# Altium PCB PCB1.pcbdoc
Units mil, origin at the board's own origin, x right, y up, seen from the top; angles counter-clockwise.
Board outline 2210 x 2265.36 mil, 2 copper layers (Top Layer, Bottom Layer); 43 components, 41 nets, 201 pads, 91 vias.
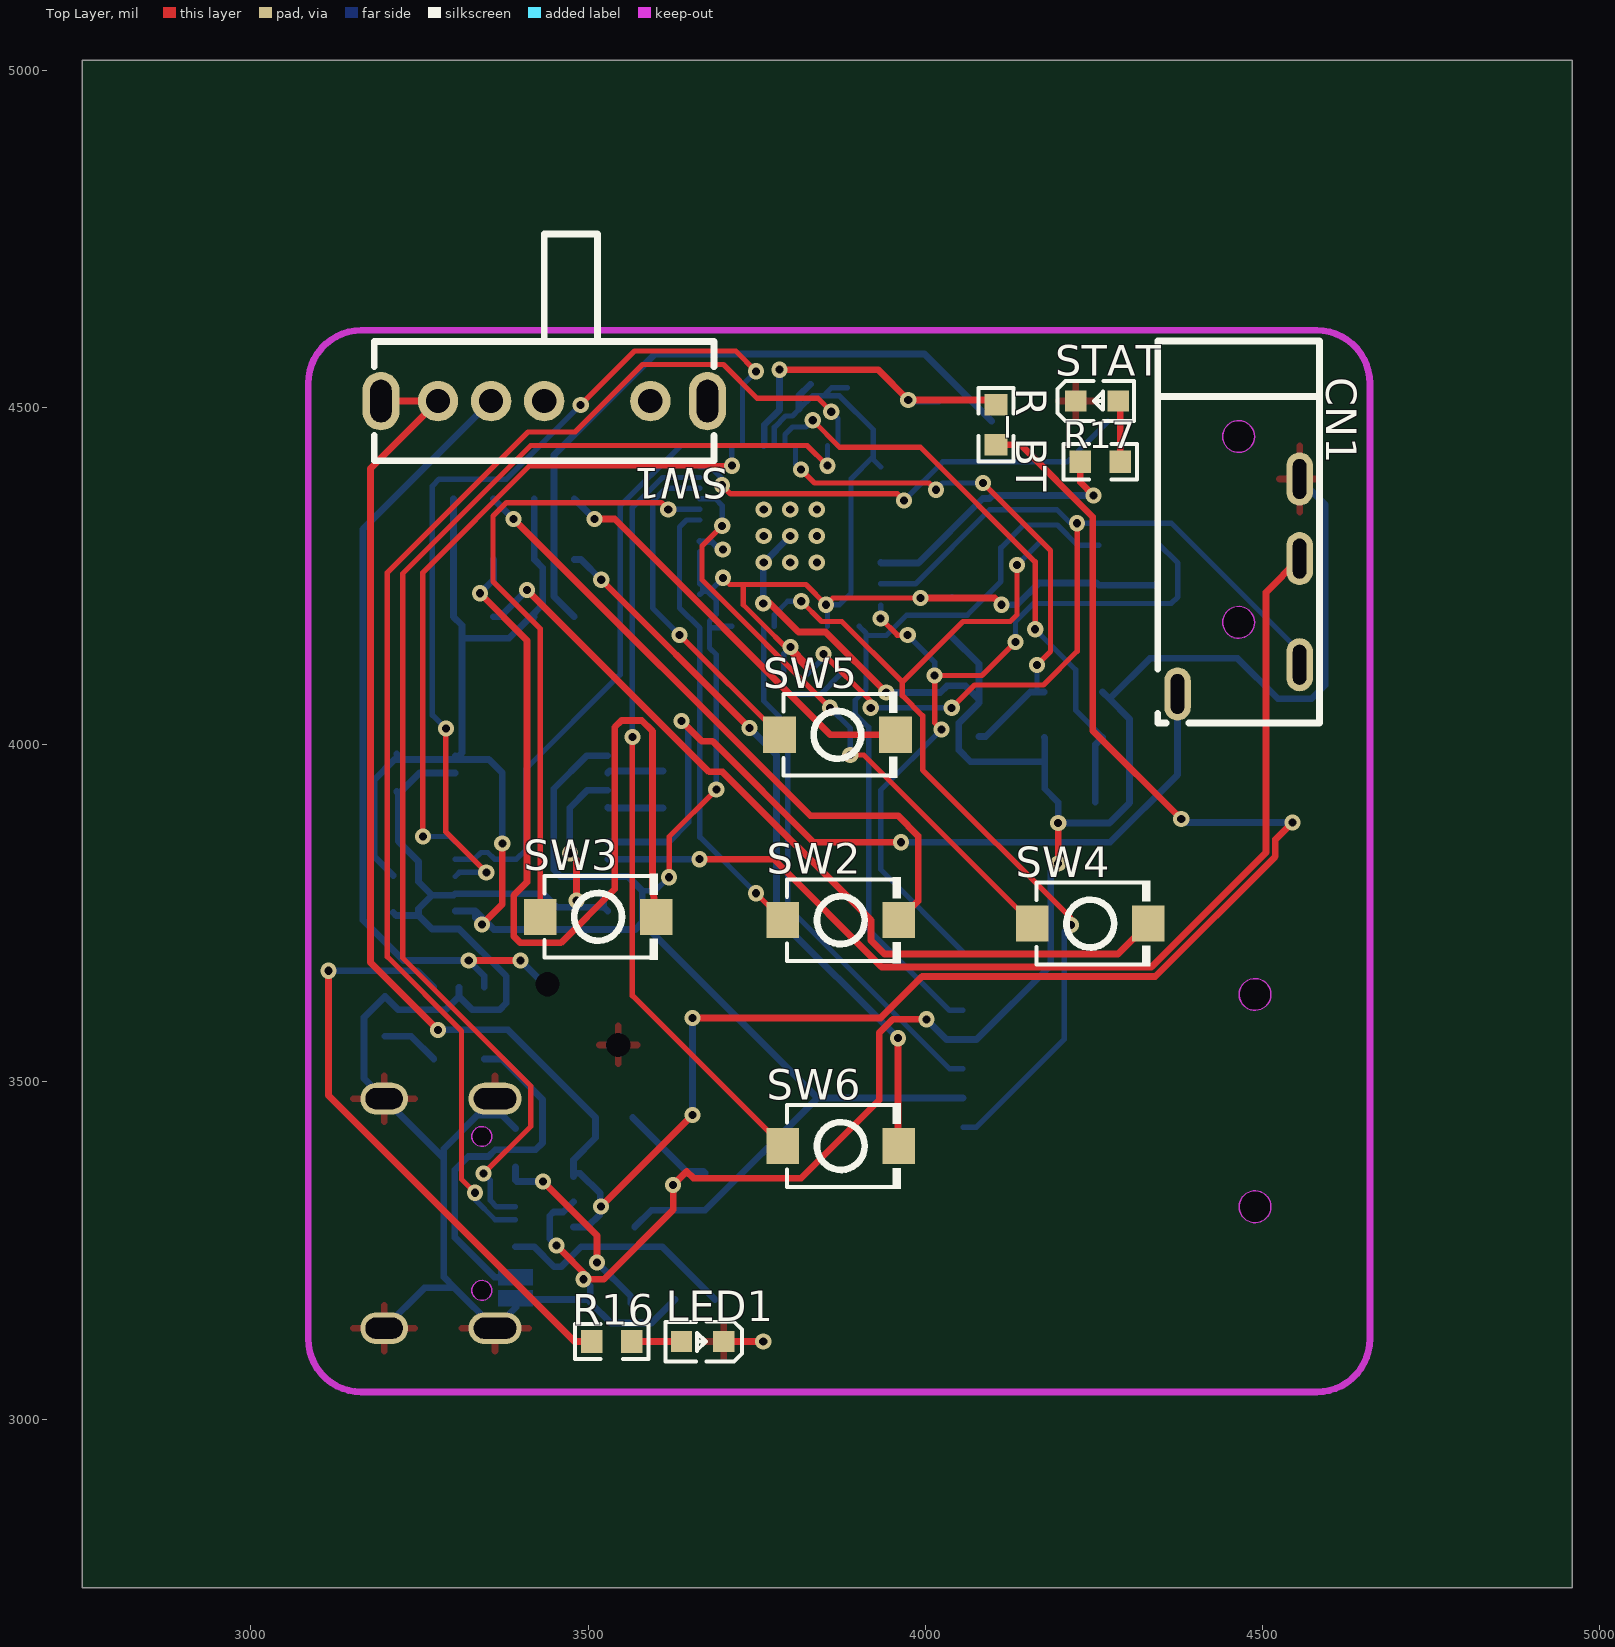
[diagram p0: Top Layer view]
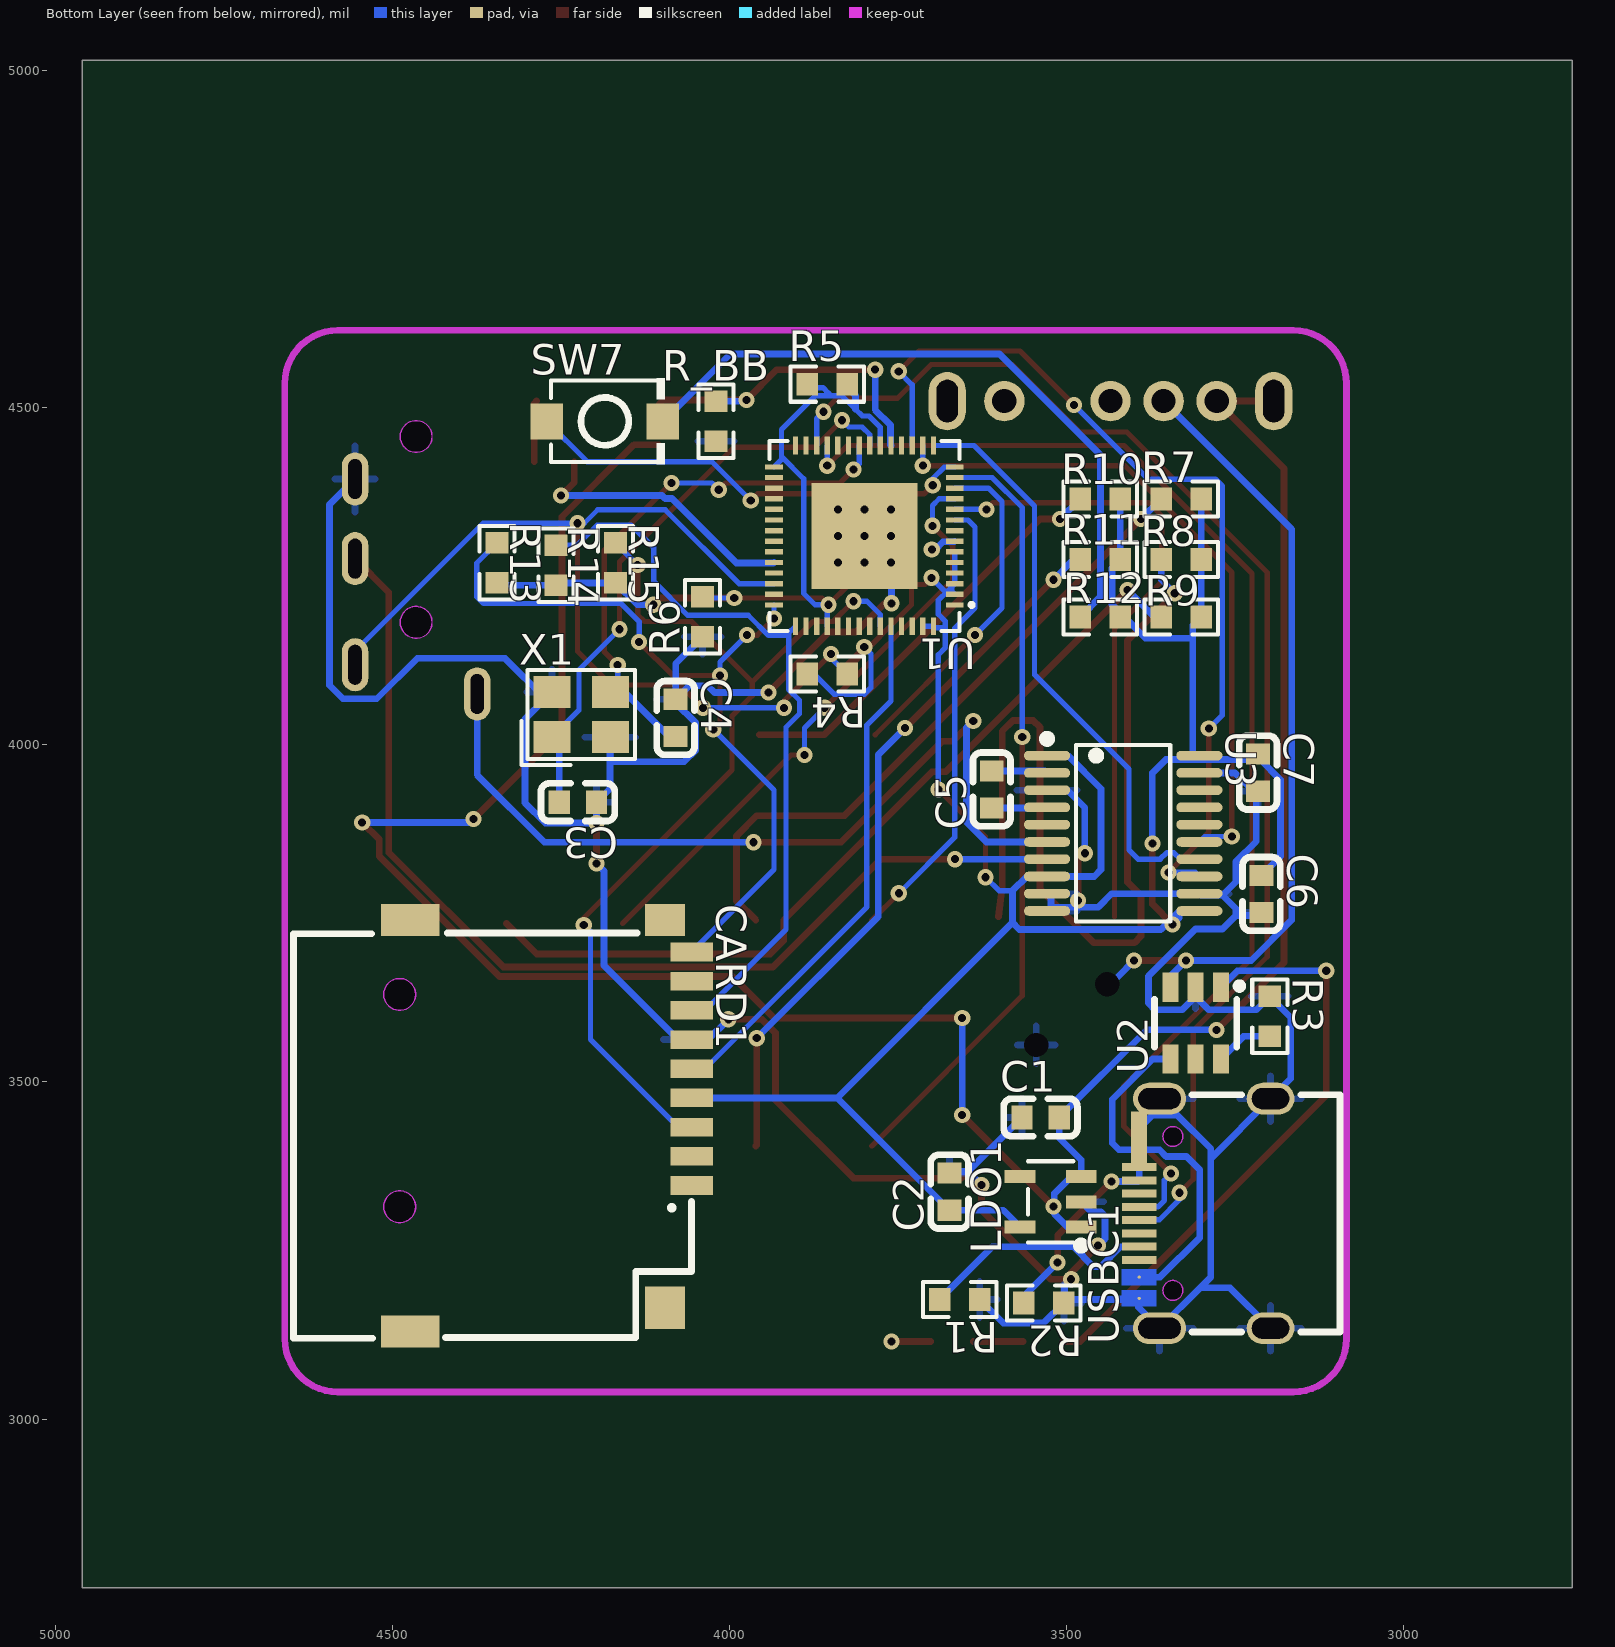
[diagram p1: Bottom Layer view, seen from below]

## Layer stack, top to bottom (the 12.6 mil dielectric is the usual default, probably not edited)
Top Layer: signal copper (thickness not stored)
Dielectric: dielectric 12.6, FR-4, Dk 4.8
Bottom Layer: signal copper (thickness not stored)

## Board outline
4960,2750 2750,2750 2750,5015.36 4960,5015.36

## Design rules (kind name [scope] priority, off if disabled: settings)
BoardOutlineClearance copperThickness1oz [All] p0: genericclearance=10 ignorepadtopadclearanceinfootprint=FALSE except(0: Arc-SplitContinuation Track-SplitContinuation SMDPad-SplitContinuation THPad-SplitContinuation Via-SplitContinuation Fill-SplitContinuation Poly-SplitContinuation Region-SplitContinuation Text-SplitContinuation; 6: Track-CutoutEdge SMDPad-CutoutEdge THPad-CutoutEdge Via-CutoutEdge Region-CutoutEdge; 11.8: Track-OutlineEdge SMDPad-OutlineEdge THPad-OutlineEdge Via-OutlineEdge Fill-OutlineEdge Region-OutlineEdge Poly-OutlineEdge Text-OutlineEdge Fill-CutoutEdge)
BoardOutlineClearance copperThickness2oz [All] p0: genericclearance=10 ignorepadtopadclearanceinfootprint=FALSE except(0: Arc-SplitContinuation Track-SplitContinuation SMDPad-SplitContinuation THPad-SplitContinuation Via-SplitContinuation Fill-SplitContinuation Poly-SplitContinuation Region-SplitContinuation Text-SplitContinuation; 6: Track-CutoutEdge SMDPad-CutoutEdge THPad-CutoutEdge Via-CutoutEdge Region-CutoutEdge; 11.8: Track-OutlineEdge SMDPad-OutlineEdge THPad-OutlineEdge Via-OutlineEdge Fill-OutlineEdge Region-OutlineEdge Poly-OutlineEdge Text-OutlineEdge Fill-CutoutEdge)
Clearance copperThickness1oz [(InNet('V_LDO_IN') OR InNet('GND') OR InNet('VCC') OR InNet('$1N1223') OR InNet('$1N1229') OR InNet('$1N2848') OR InNet('$1N2853') OR InNet('TF_DATA0') OR InNet('TF_CLX') OR InNet('TF_CMD') OR InNet('TF_CD') OR InNet('OUTR') OR InNet('GPIO35') OR InNet('OUTL') OR InNet('$1N2072') OR InNet('$1N2076') OR InNet('$1N2223') OR InNet('$1N3768') OR InNet('$1N3800') OR InNet('$1N3832') OR InNet('$1N3864') OR InNet('$1N3896') OR InNet('$1N3928') OR InNet('V_BAT') OR InNet('B1') OR InNet('B2') OR InNet('B3') OR InNet('B4') OR InNet('B5') OR InNet('B6') OR InNet('I2S_DATA') OR InNet('I2S_LRCK') OR InNet('I2S_BCK') OR InNet('USB_DN') OR InNet('USB_DP') OR InNet('V_USB') OR InNet('$1N4567') OR InNet('$1N4573') OR InNet('ADC') OR InNet('LED_STAT') OR InNet('$1N5751'))] p1: gap=7 ignorepadtopadclearanceinfootprint=FALSE except(4: Track-Track; 6: Track-SMDPad SMDPad-SMDPad Track-THPad SMDPad-THPad THPad-THPad Track-Via SMDPad-Via THPad-Via Via-Via SMDPad-Fill THPad-Fill Via-Fill Fill-Fill Track-Region SMDPad-Region THPad-Region Via-Region Region-Region Track-Poly SMDPad-Poly THPad-Poly Via-Poly Fill-Poly Region-Poly Poly-Poly Track-Text SMDPad-Text THPad-Text Via-Text Fill-Text Region-Text Poly-Text Text-Text; 6.9: Track-Hole SMDPad-Hole THPad-Hole Via-Hole Fill-Hole Region-Hole Poly-Hole Text-Hole Sheet-Hole; 11.8: Track-Fill Fill-Region Track-Sheet SMDPad-Sheet THPad-Sheet Via-Sheet Fill-Sheet Region-Sheet Poly-Sheet Text-Sheet)
Clearance copperThickness2oz [All] p1: gap=7 ignorepadtopadclearanceinfootprint=FALSE except(6: Track-SMDPad SMDPad-SMDPad Track-THPad SMDPad-THPad THPad-THPad Track-Via SMDPad-Via THPad-Via Via-Via SMDPad-Fill THPad-Fill Via-Fill Fill-Fill Track-Region SMDPad-Region THPad-Region Via-Region Region-Region Track-Poly SMDPad-Poly THPad-Poly Via-Poly Fill-Poly Region-Poly Poly-Poly Track-Text SMDPad-Text THPad-Text Via-Text Fill-Text Region-Text Poly-Text Text-Text; 6.9: Track-Hole SMDPad-Hole THPad-Hole Via-Hole Fill-Hole Region-Hole Poly-Hole Text-Hole Sheet-Hole; 8: Track-Track; 11.8: Track-Fill Fill-Region Track-Sheet SMDPad-Sheet THPad-Sheet Via-Sheet Fill-Sheet Region-Sheet Poly-Sheet Text-Sheet)
DiffPairsRouting differentialPair [All] p1: maxuncoupledlength=10 minlimit=6 maxlimit=6 mostfreqgap=6 toplayer_minwidth=5 toplayer_prefwidth=10 toplayer_maxwidth=100 bottomlayer_minwidth=5 bottomlayer_prefwidth=10 bottomlayer_maxwidth=100
PasteMaskExpansion pasteMaskExpansion [All] p1: expansion=0
PlaneConnect innerPlane [All] p1: planeconnectstyle=Relief reliefexpansion=20 reliefentries=4 reliefconductorwidth=10 reliefairgap=10
PolygonConnect copperRegion [All] p1: connectstyle=Relief reliefentries=4 reliefconductorwidth=10 polygonreliefangle="90 Angle" airgapwidth=10
RoutingVias viaSize [All] p1: viastyle="Through Hole" holewidth=12.0078 minholewidth=11.811 maxholewidth=248.0314 width=24.0158 minwidth=19.685 maxwidth=393.7008
SolderMaskExpansion solderMaskExpansion [All] p1: useseparateexpansions=TRUE expansion=2 expansionbottom=2
Width copperThickness1oz [All] p1: maxlimit=100 minlimit=5 preferedwidth=10
Width copperThickness2oz [All] p1: maxlimit=100 minlimit=8 preferedwidth=10

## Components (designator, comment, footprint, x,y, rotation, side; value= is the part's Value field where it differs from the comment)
C1 "CL10A106MA8NRNC" C0603 3538.72,3447.33 r180 bottom
C2 "CL10A106MA8NRNC" C0603 3673.72,3337.33 r90 bottom
C3 "CL10C100JB8NNNC" C0603 4225,3915 r0 bottom
C4 "CL10C100JB8NNNC" C0603 4080,4040 r270 bottom
C5 "CL10B104KB8NNNC" C0603 3611.11,3933.89 r90 bottom
C6 "CL10B104KB8NNNC" C0603 3211.11,3778.89 r270 bottom
C7 "CL10B104KB8NNNC" C0603 3216.11,3958.89 r270 bottom
CARD1 "TF PUSH" TF-SMD_TF-PUSH 4265,3435 r270 bottom
CN1 "PJ-320A_C49284721" AUDIO-TH_PJ-320A_C49284721 4465,4235 r270 top
LDO1 "ME6211C33M5G-N" SOT-23-5_L3.0-W1.7-P0.95-LS2.8-BL 3523.72,3322.33 r90 bottom
LED1 "NCD0603Y2" LED0603-RD 3670,3115 r180 top
R1 "0603WAF5101T5E" R0603 3658.72,3177.33 r0 bottom
R2 "0603WAF5101T5E" R0603 3533.72,3172.33 r0 bottom
R3 "ERA3AEB162V" R0603 3198.72,3597.33 r270 bottom
R4 "0603WAF1002T5E" R0603 3855,4105 r0 bottom
R5 "0603WAF1002T5E" R0603 3855,4535 r180 bottom
R6 "0603WAF1002T5E" R0603 4040,4190 r90 bottom
R7 "0603WAF1002T5E" R0603 3330,4365 r180 bottom
R8 "0603WAF1002T5E" R0603 3330,4275 r180 bottom
R9 "0603WAF1002T5E" R0603 3330,4190 r180 bottom
R10 "0603WAF1002T5E" R0603 3450,4365 r180 bottom
R11 "0603WAF1002T5E" R0603 3450,4275 r180 bottom
R12 "0603WAF1002T5E" R0603 3450,4190 r180 bottom
R13 "0603WAF1002T5E" R0603 4345,4270 r270 bottom
R14 "0603WAF1002T5E" R0603 4257.65,4266.48 r270 bottom
R15 "0603WAF1002T5E" R0603 4169.01,4270 r270 bottom
R16 "FRC0603J221 TS" R0603 3535,3115 r0 top
R17 "Res_0603" R0603 4260,4420 r0 top
R_BB "Res_0603" R0603 4020,4480 r270 bottom
R_BT "Res_0603" R0603 4105,4475 r90 top
STAT "NCD0603Y2" LED0603-RD 4255,4510 r0 top
SW1 "SK13D07VG4" SW-TH_SK13D07VG4 3435,4510 r180 top
SW2 "TS-1088-AR02016" SW-SMD_L3.9-W3.0-P4.45 3875,3740 r0 top
SW3 "TS-1088-AR02016" SW-SMD_L3.9-W3.0-P4.45 3515,3745 r0 top
SW4 "TS-1088-AR02016" SW-SMD_L3.9-W3.0-P4.45 4245,3735 r0 top
SW5 "TS-1088-AR02016" SW-SMD_L3.9-W3.0-P4.45 3870,4015 r0 top
SW6 "TS-1088-AR02016" SW-SMD_L3.9-W3.0-P4.45 3875,3405 r0 top
SW7 "TS-1088-AR02016" SW-SMD_L3.9-W3.0-P4.45 4185,4480 r180 bottom
U1 "ESP32-S3R8" QFN-56_L7.0-W7.0-P0.40-TL-EP4.0 3800,4310 r0 bottom
U2 "TP4057" SOT-23-6_L2.9-W1.6-P0.95-LS2.8-BR 3308.72,3587.33 r90 bottom
U3 "PCM5100APWR" TSSOP-20_L6.5-W4.4-P0.65-LS6.4-BL 3416.11,3868.89 r270 bottom
USBC1 "TYPE-C-31-M-12" USB-C_SMD-TYPE-C-31-M-12_1 3295,3305 r90 bottom
X1 "XL2EL89CPI-111YLC-40M" CRYSTAL-SMD_4P-L3.2-W2.5-BL 4220,4045 r180 bottom

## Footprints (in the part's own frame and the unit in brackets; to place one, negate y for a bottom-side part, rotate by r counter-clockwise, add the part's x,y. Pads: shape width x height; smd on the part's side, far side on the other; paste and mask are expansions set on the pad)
AUDIO-TH_PJ-320A_C49284721 [mm]
  oval 2x1 hole 0.5 slot 1.5 at 0 deg: 2(4.05,-2.3) 3(-1.05,2.3) 4(2.95,2.3) 5(-4.05,2.3)
  Board Outline Layer circle w0.005: c-5.65,0 r0.6
  Board Outline Layer circle w0.005: c1.35,0 r0.6
  Board Outline Layer region: -5.65,0.6 -5.39,0.541 -5.181,0.374 -5.065,0.134 -5.065,-0.134 -5.181,-0.374 -5.39,-0.541 -5.65,-0.6 -5.65,-0.6 -5.91,-0.541 -6.119,-0.374 -6.235,-0.134 -6.235,0.134 -6.119,0.374 -5.91,0.541 -5.65,0.6
  Board Outline Layer region: 1.35,0.6 1.61,0.541 1.819,0.374 1.935,0.134 1.935,-0.134 1.819,-0.374 1.61,-0.541 1.35,-0.6 1.35,-0.6 1.09,-0.541 0.881,-0.374 0.765,-0.134 0.765,0.134 0.881,0.374 1.09,0.541 1.35,0.6
  Multi-Layer board cut-out: -5.65,0.6 -5.39,0.541 -5.181,0.374 -5.065,0.134 -5.065,-0.134 -5.181,-0.374 -5.39,-0.541 -5.65,-0.6 -5.65,-0.6 -5.91,-0.541 -6.119,-0.374 -6.235,-0.134 -6.235,0.134 -6.119,0.374 -5.91,0.541 -5.65,0.6
  Multi-Layer board cut-out: 1.35,0.6 1.61,0.541 1.819,0.374 1.935,0.134 1.935,-0.134 1.819,-0.374 1.61,-0.541 1.35,-0.6 1.35,-0.6 1.09,-0.541 0.881,-0.374 0.765,-0.134 0.765,0.134 0.881,0.374 1.09,0.541 1.35,0.6
  silkscreen extent -9.25,-3.05 5.14,3.05
C0603 [mm]
  rect 0.8x0.9 smd: 1(-0.7,0) 2(0.7,0)
  silkscreen extent -1.39,-0.71 1.39,0.71
CRYSTAL-SMD_4P-L3.2-W2.5-BL [mm]
  rect 1.4x1.2 smd: 1(-1.1,-0.85) 2(1.1,-0.85) 3(1.1,0.85) 4(-1.1,0.85)
  silkscreen extent -2.26,-1.91 2.03,1.68
LED0603-RD [mm]
  rect 0.8x0.8 smd: 1(-0.799,0) 2(0.799,0)
  silkscreen extent -1.49,-0.75 1.39,0.76
QFN-56_L7.0-W7.0-P0.40-TL-EP4.0 [mm]
  rect 0.665x0.2 smd: 1(-3.408,2.6) 2(-3.408,2.2) 3(-3.408,1.8) 4(-3.408,1.4) 5(-3.408,1) 6(-3.408,0.6) 7(-3.408,0.2) 8(-3.408,-0.2) 9(-3.408,-0.6) 10(-3.408,-1) 11(-3.408,-1.4) 12(-3.408,-1.8) 13(-3.408,-2.2) 14(-3.408,-2.6) 29(3.408,-2.6) 30(3.408,-2.2) 31(3.408,-1.8) 32(3.408,-1.4) 33(3.408,-1) 34(3.408,-0.6) 35(3.408,-0.2) 36(3.408,0.2) 37(3.408,0.6) 38(3.408,1) 39(3.408,1.4) 40(3.408,1.8) 41(3.408,2.2) 42(3.408,2.6)
  rect 0.2x0.665 smd: 15(-2.6,-3.408) 16(-2.2,-3.408) 17(-1.8,-3.408) 18(-1.4,-3.408) 19(-1,-3.408) 20(-0.6,-3.408) 21(-0.2,-3.408) 22(0.2,-3.408) 23(0.6,-3.408) 24(1,-3.408) 25(1.4,-3.408) 26(1.8,-3.408) 27(2.2,-3.408) 28(2.6,-3.408) 43(2.6,3.408) 44(2.2,3.408) 45(1.8,3.408) 46(1.4,3.408) 47(1,3.408) 48(0.6,3.408) 49(0.2,3.408) 50(-0.2,3.408) 51(-0.6,3.408) 52(-1,3.408) 53(-1.4,3.408) 54(-1.8,3.408) 55(-2.2,3.408) 56(-2.6,3.408)
  rect 4x4 smd: 57(0,0)
  silkscreen extent -4.11,-3.58 3.58,3.58
R0603 [mil]
  rect 31.75x34.02 smd: 1(-29.66,0) 2(29.66,0)
  silkscreen extent -55,-26 55,26
SOT-23-5_L3.0-W1.7-P0.95-LS2.8-BL [mm]
  rect 0.49x1.157 smd: 1(-0.95,-1.154) 2(0,-1.154) 3(0.95,-1.154)
  rect 0.49x1.175 smd: 4(0.95,1.154) 5(-0.95,1.154)
  silkscreen extent -1.8,-1.29 1.53,0.85
SOT-23-6_L2.9-W1.6-P0.95-LS2.8-BR [mm]
  rect 1.1x0.6 smd: 1(1.35,-0.95) 2(1.35,0) 3(1.35,0.95) 4(-1.35,0.95) 5(-1.35,0) 6(-1.35,-0.95)
  silkscreen extent -0.9,-1.78 1.52,1.55
SW-SMD_L3.9-W3.0-P4.45 [mm]
  rect 1.23x1.36 smd: 1(-2.185,0) 2(2.185,0)
  silkscreen extent -2.03,-1.62 2.25,1.62
SW-TH_SK13D07VG4 [mil]
  round 60 hole 36: 1(-157.48,0) 3(0,0) 4(78.74,0) 5(157.48,0)
  oval 55.12x86.61 hole 31.5 slot 62.99 at 90 deg: 6(242.13,0) 7(-242.13,0)
  silkscreen extent -252,-248 252,89
TF-SMD_TF-PUSH [mm]
  rect 0.7x1.6 smd: 1(2.25,5.3) 2(1.15,5.3) 3(0.05,5.3) 4(-1.05,5.3) 5(-2.15,5.3) 6(-3.25,5.3) 7(-4.35,5.3) 8(-5.45,5.3) CD(-6.55,5.3)
  rect 1.2x1.5 smd: 10(-7.75,4.3)
  rect 1.2x2.2 smd: 11(-7.75,-5.3) 12(7.75,-5.3)
  rect 1.6x1.5 smd: 13(6.85,4.3)
  Board Outline Layer circle w0.005: c-4.95,-5.7 r0.6
  Board Outline Layer circle w0.005: c3.05,-5.7 r0.6
  Board Outline Layer region: -4.95,-6.3 -4.69,-6.241 -4.481,-6.074 -4.365,-5.834 -4.365,-5.567 -4.481,-5.326 -4.69,-5.159 -4.95,-5.1 -4.95,-5.1 -5.21,-5.159 -5.419,-5.326 -5.535,-5.567 -5.535,-5.834 -5.419,-6.074 -5.21,-6.241 -4.95,-6.3
  Board Outline Layer region: 3.05,-6.3 3.31,-6.241 3.519,-6.074 3.635,-5.834 3.635,-5.567 3.519,-5.326 3.31,-5.159 3.05,-5.1 3.05,-5.1 2.79,-5.159 2.581,-5.326 2.465,-5.567 2.465,-5.834 2.581,-6.074 2.79,-6.241 3.05,-6.3
  Multi-Layer board cut-out: -4.95,-6.3 -4.69,-6.241 -4.481,-6.074 -4.365,-5.834 -4.365,-5.567 -4.481,-5.326 -4.69,-5.159 -4.95,-5.1 -4.95,-5.1 -5.21,-5.159 -5.419,-5.326 -5.535,-5.567 -5.535,-5.834 -5.419,-6.074 -5.21,-6.241 -4.95,-6.3
  Multi-Layer board cut-out: 3.05,-6.3 3.31,-6.241 3.519,-6.074 3.635,-5.834 3.635,-5.567 3.519,-5.326 3.31,-5.159 3.05,-5.1 3.05,-5.1 2.79,-5.159 2.581,-5.326 2.465,-5.567 2.465,-5.834 2.581,-6.074 2.79,-6.241 3.05,-6.3
  silkscreen extent -7.26,-9.7 8,5.3
TSSOP-20_L6.5-W4.4-P0.65-LS6.4-BL [mil]
  oval 14.33x68.58 smd: 1(-115.16,-113.03) 2(-89.57,-113.03) 3(-63.98,-113.03) 4(-38.39,-113.03) 5(-12.79,-113.03) 6(12.8,-113.03) 7(38.39,-113.03) 8(63.98,-113.03) 9(89.57,-113.03) 10(115.16,-113.03) 11(115.16,113.03) 12(89.57,113.03) 13(63.98,113.03) 14(38.39,113.03) 15(12.8,113.03) 16(-12.79,113.03) 17(-38.39,113.03) 18(-63.98,113.03) 19(-89.57,113.03) 20(-115.16,113.03)
  silkscreen extent -146,-119 131,70
USB-C_SMD-TYPE-C-31-M-12_1 [mm]
  oval 1.2x2 hole 0.8 slot 1.6 at 90 deg: 1(4.325,1.706) 4(-4.325,1.706)
  oval 1.2x1.8 hole 0.8 slot 1.4 at 90 deg copper offset 0,0: 2(4.325,-2.474) 3(-4.325,-2.474)
  round 0.12 smd: A1B12(-3.2,2.474) A4B9(-2.4,2.474)
  rect 0.3x1.3 smd: A5(-1.25,2.474) A6(-0.25,2.474) A7(0.25,2.474) A8(1.25,2.474) B5(1.75,2.474) B6(0.75,2.474) B7(-0.75,2.474) B8(-1.75,2.474)
  rect 1.3x0.6 smd: B1A12(3.2,2.474) B4A9(2.4,2.474)
  Top Layer region: -2.9,1.824 -2.9,3.124 -3.2,3.124 -3.2,3.124 -3.5,3.124 -3.5,1.824 -3.2,1.824 -3.2,1.824
  Top Layer region: -2.1,1.824 -2.1,3.124 -2.4,3.124 -2.4,3.124 -2.7,3.124 -2.7,1.824 -2.4,1.824 -2.4,1.824
  Board Outline Layer circle w0.005: c-2.9,1.206 r0.375
  Board Outline Layer circle w0.005: c2.9,1.206 r0.375
  Board Outline Layer region: -2.9,1.581 -3.063,1.543 -3.193,1.439 -3.266,1.289 -3.266,1.122 -3.193,0.972 -3.063,0.868 -2.9,0.831 -2.9,0.831 -2.737,0.868 -2.607,0.972 -2.534,1.122 -2.534,1.289 -2.607,1.439 -2.737,1.543 -2.9,1.581
  Board Outline Layer region: 2.9,1.581 2.737,1.543 2.607,1.439 2.534,1.289 2.534,1.122 2.607,0.972 2.737,0.868 2.9,0.831 2.9,0.831 3.063,0.868 3.193,0.972 3.266,1.122 3.266,1.289 3.193,1.439 3.063,1.543 2.9,1.581
  Multi-Layer board cut-out: -2.9,1.581 -3.063,1.543 -3.193,1.439 -3.266,1.289 -3.266,1.122 -3.193,0.972 -3.063,0.868 -2.9,0.831 -2.9,0.831 -2.737,0.868 -2.607,0.972 -2.534,1.122 -2.534,1.289 -2.607,1.439 -2.737,1.543 -2.9,1.581
  Multi-Layer board cut-out: 2.9,1.581 2.737,1.543 2.607,1.439 2.534,1.289 2.534,1.122 2.607,0.972 2.737,0.868 2.9,0.831 2.9,0.831 3.063,0.868 3.193,0.972 3.266,1.122 3.266,1.289 3.193,1.439 3.063,1.543 2.9,1.581
  silkscreen extent -4.47,-5.09 4.47,0.49

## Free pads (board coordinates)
  round 31.5 hole 36: 1(3440,3645) 1(3545,3555)

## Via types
v1: diameter 24.02, hole 12.01, Top Layer to Bottom Layer, 82 vias
v2: diameter 24, hole 12, Top Layer to Bottom Layer, 9 vias

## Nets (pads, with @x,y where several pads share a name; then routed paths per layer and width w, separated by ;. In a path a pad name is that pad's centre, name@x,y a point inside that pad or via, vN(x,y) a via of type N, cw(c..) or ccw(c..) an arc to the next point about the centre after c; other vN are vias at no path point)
$1N1223: C3.2 U1.21 X1.1 | length 885.5
  Top Layer w7.87: v1(3833.31,4481.53) 3873.31,4441.53 3993.31,4441.53 4163.31,4271.53 v1(4163.31,4171.53)
  Bottom Layer w7.87: U1.21 3792.12,4460.35 3803.31,4471.53 3823.31,4471.53 v1(3833.31,4481.53) ; v1(4163.31,4171.53) 4223.31,4111.53 4223.31,4051.53 X1.1
  Bottom Layer w10: C3.2 4252.56,4000.78 X1.1
$1N1229: C4.2 U1.22 X1.3 | length 809.4
  Top Layer w7.87: v1(3816.03,4408.47) 3836.03,4388.47 4006.03,4388.47 v1(4016.03,4378.47) ; v1(4086.03,4388.47) 4186.02,4288.47 4186.02,4138.47 v1(4166.02,4118.47)
  Bottom Layer w7.87: U1.22 3807.88,4416.61 v1(3816.03,4408.47) ; v1(4016.03,4378.47) 4026.03,4388.47 v1(4086.03,4388.47) ; X1.3@4166.02,4078.47 v1(4166.02,4118.47)
  Bottom Layer w10: C4.2 4090,4012.44 4156.02,4078.47 4166.02,4078.47 X1.3
$1N2072: R1.2 USBC1.A5 | length 353.3
  Bottom Layer w10: USBC1.A5 3419.92,3255.79 3449.92,3225.79 3459.92,3225.79 3489.92,3255.79 3609.92,3255.79 R1.2
$1N2076: R2.2 USBC1.A8 USBC1.B5 | length 295.3
  Top Layer w10: v1(3433.38,3352.33) 3513.38,3272.33 v1(3513.38,3232.33)
  Bottom Layer w10: USBC1.B5 USBC1.A8 3394.28,3352.33 v1(3433.38,3352.33) ; v1(3513.38,3232.33) 3563.38,3182.33 R2.2
$1N2223: R3.2 U2.6 | length 86.5
  Bottom Layer w10: R3.2 3237.83,3567.67 U2.6
$1N2848: C5.2 U3.2 | length 83.2
  Bottom Layer w10: U3.2 3532.13,3961.45 C5.2
$1N2853: C5.1 U3.4 | length 82.4
  Bottom Layer w10: U3.4 3530.1,3906.33 C5.1
$1N3768: R7.1 SW2.2 | length 974
  Top Layer w10: v1(3389.66,4335) 3829.66,3895 3959.66,3895 3989.66,3865 3989.66,3768.64 SW2.2
  Bottom Layer w10: R7.1 v1(3389.66,4335)
$1N3800: R8.1 SW3.2 | length 1373.9
  Top Layer w10: v1(3339.66,4225) 3409.66,4155 3409.66,3796.36 3389.66,3776.36 3389.66,3716.36 3399.66,3706.36 3459.66,3706.36 3539.66,3786.36 3539.66,4026.36 3549.66,4036.36 3579.66,4036.36 3595.6,4020.42 3595.6,3790.24 SW3.2
  Bottom Layer w10: v1(3339.66,4225) 3359.66,4245 R8.1
$1N3832: R9.1 SW4.2 | length 1247.8
  Top Layer w10: v1(3409.66,4230) 3679.66,3960 3699.66,3960 3919.66,3740 3919.66,3710 3939.66,3690 4286.02,3690 SW4.2
  Bottom Layer w10: R9.1 3369.66,4190 v1(3409.66,4230)
$1N3864: R10.1 SW5.2 | length 621.3
  Top Layer w10: v1(3509.66,4335) 3539.66,4335 3859.66,4015 SW5.2
  Bottom Layer w10: R10.1 v1(3509.66,4335)
$1N3896: R11.1 SW6.2 | length 1075.2
  Top Layer w10: v1(3519.66,4245) v1(3739.66,4025) ; v1(3959.66,3565) 3959.66,3406.36 SW6.2
  Bottom Layer w10: R11.1 3489.66,4275 v1(3519.66,4245) ; v1(3739.66,4025) 3779.66,3985 3779.66,3745 v1(3959.66,3565)
$1N3928: R12.1 SW7.2 | length 1005.3
  Bottom Layer w10: R12.1 3449.66,4220 3449.66,4430 3599.66,4580 3998.98,4580 SW7.2
$1N4567: R16.1 U2.1 | length 893
  Top Layer w10: v1(3115,3665) 3115,3480 3480,3115 R16.1
  Bottom Layer w10: v1(3115,3665) 3246.8,3665 U2.1
$1N4573: LED1.2 R16.2 | length 73.9
  Top Layer w10: R16.2 LED1.2
$1N5751: R17.2 STAT.2 | length 91.3
  Top Layer w10: STAT.2 4289.66,4506.82 R17.2
ADC: R_BB.1 R_BT.2 U1.19 | length 510.5
  Top Layer w10: v1(3784.02,4556.61) 3930,4556.61 v1(3975,4511.61) 4098.05,4511.61 R_BT.2
  Bottom Layer w10: U1.19 3761.46,4444.98 3761.46,4474.48 3784.02,4497.04 v1(3784.02,4556.61) ; v1(3975,4511.61) 3976.95,4509.66 R_BB.1
B1: SW2.1 U1.9 | length 680.9
  Top Layer w7.87: v1(3748.98,3780) SW2.1
  Bottom Layer w7.87: U1.9 3646.32,4333.61 3635.84,4323.14 3635.84,4203.14 3665.84,4173.14 3665.84,3863.14 v1(3748.98,3780)
B2: SW3.1 U1.10 | length 942.7
  Top Layer w7.87: SW3.1 3428.98,4172.5 3358.98,4242.5 3358.98,4339.36 3378.98,4359.36 3608.98,4359.36 v1(3618.98,4349.36)
  Bottom Layer w7.87: v1(3618.98,4349.36) U1.10
B3: SW4.1 U1.11 | length 884.5
  Top Layer w7.87: v1(3698.98,4325) 3668.98,4295 3668.98,4245 v1(3858.98,4055) ; v1(3888.98,3985) 3908.98,3985 SW4.1
  Bottom Layer w7.87: U1.11 3688.98,4365.11 3698.98,4355.11 v1(3698.98,4325) ; v1(3858.98,4055) 3888.98,4025 v1(3888.98,3985)
B4: SW5.1 U1.12 | length 502.1
  Top Layer w7.87: v1(3635.84,4163.14) SW5.1
  Bottom Layer w7.87: v1(3635.84,4163.14) 3595.84,4203.14 3595.84,4360.86 3615.84,4380.86 U1.12
B5: SW6.1 U1.13 | length 1157.8
  Top Layer w7.87: v1(3565.84,4011.86) 3565.84,3628.14 SW6.1
  Bottom Layer w7.87: v1(3565.84,4011.86) 3565.84,4351.86 3610.59,4396.61 U1.13
B6: SW7.1 U1.14 | length 680.5
  Top Layer w7.87: v1(3698.66,4385.18) 3711.49,4372.35 3958.66,4372.35 v1(3968.66,4362.35)
  Bottom Layer w7.87: U1.14 3681.49,4412.35 3698.66,4395.18 v1(3698.66,4385.18) ; v1(3968.66,4362.35) 4026.31,4420 4211.02,4420 SW7.1
GND: C1.1 C2.2 C3.1 C4.1 C6.2 C7.2 CARD1.6 CN1.5 LDO1.2 LED1.1 pad.1@3545,3555 R1.1 R2.1 R3.1 R6.1 R_BB.2 STAT.1 U1.57 U2.2 U3.3 U3.9 U3.10 U3.12 U3.19 USBC1.1 USBC1.2 USBC1.3 USBC1.4 USBC1.A1B12 USBC1.B1A12 X1.2 X1.4 | length 6124.4
  Top Layer w10: v1(3453.3,3257.33) v1@3503.3,3207.33 ; v1(3473.08,3839.32) 3483.08,3829.32 v1(3483.08,3769.32) ; v1(3493.3,3207.33) v1@3503.3,3207.33 ; LED1.1 v1(3760,3115.01) ; v1(3760.01,4209.99) 3770.01,4209.99 3812.44,4167.56 3852.44,4167.56 v1(3942.44,4077.56) ; v1(4001.91,3592.95) 3951.91,3592.95 3931.91,3572.95 3931.91,3472.95 3816.28,3357.33 3656.28,3357.33 3646.28,3367.33 v1(3626.28,3347.33) 3626.28,3310.31 3523.3,3207.33 v1@3503.3,3207.33 ; v1(4197.44,3824.05) v1(4197.44,3884.05)
  Bottom Layer w10: USBC1.3 3257.59,3194.72 3302.16,3194.72 ; C6.2 3215.45,3746.99 3248.72,3746.99 ; C7.2 C7.2@3218.72,3926.99 ; U3.19 3250.2,3958.46 C7.2@3218.72,3926.99 ; U2.2 U2.2@3308.72,3626.99 ; USBC1.1 3346.14,3459.26 3346.14,3450.99 ; USBC1.A1B12 USBC1.A1B12@3393.3,3177.33 ; USBC1.B1A12 3372.41,3450.99 3346.14,3450.99 ; v1(3453.3,3257.33) 3443.3,3267.33 3443.3,3301.56 3449.07,3307.33 3463.3,3307.33 LDO1.2 ; v1(3473.08,3839.32) 3473.08,3906.81 3499.14,3932.87 U3.3 ; v1(3483.08,3769.32) v1@3483.08,3759.32 ; v1(3493.3,3207.33) 3503.3,3197.33 R2.1@3503.3,3177.33 ; U3.10 U3.10@3523.08,3759.32 ; U3.9 3523.08,3773.26 U3.10@3523.08,3759.32 ; C1.1 3646.28,3367.33 ; v1(3626.28,3347.33) 3646.28,3367.33 ; R1.1 3594.06,3142.33 3534.06,3142.33 R2.1 3503.3,3173.09 R2.1@3503.3,3177.33 ; C2.2 3671.28,3367.33 3646.28,3367.33 ; v1(3760.01,4209.99) 3760.01,4269.99 v2(3800.01,4310.01) ; v1(3942.44,4077.56) 4022.44,4077.56 4032.44,4087.56 4060,4087.56 C4.1 ; v1(4001.91,3592.95) 4031.91,3562.95 CARD1.6 4076.34,3562.95 4186.34,3672.95 4186.34,3812.95 v1(4197.44,3824.05) ; R6.1 4080,4120.34 C4.1 ; X1.2 4177.44,4010.78 4177.44,3975 ; X1.4 X1.4@4273.31,4068.47 ; CN1.5@4555.55,4394.45 4593.31,4356.69 4593.31,4088.47 4573.31,4068.47 4523.31,4068.47 4463.31,4128.47 4333.31,4128.47 X1.4@4273.31,4068.47 ; C7.2@3218.72,3926.99 3218.72,3856.99 3248.72,3826.99 3248.72,3796.99 3268.72,3776.99 ; 3248.72,3746.99 3268.72,3726.99 3308.72,3726.99 3378.72,3656.99 3378.72,3616.99 3368.72,3606.99 3328.72,3606.99 U2.2@3308.72,3626.99 ; 3248.72,3746.99 3248.72,3756.99 3268.72,3776.99 ; 3268.72,3776.99 3300.75,3776.99 U3.12 3433.08,3779.32 3453.08,3759.32 v1@3483.08,3759.32 ; 3286.14,3386.74 USBC1.2 3167.59,3505.28 3167.59,3595.86 R3.1 3218.72,3606.99 3288.72,3606.99 U2.2@3308.72,3626.99 ; 3286.14,3386.74 3286.14,3210.74 3302.16,3194.72 ; 3286.14,3386.74 3286.14,3400.99 3336.14,3450.99 3346.14,3450.99 ; 3302.16,3194.72 USBC1.4 3393.3,3165.87 USBC1.A1B12@3393.3,3177.33 ; USBC1.A1B12@3393.3,3177.33 R2.1@3503.3,3177.33 ; v1@3483.08,3759.32 U3.10@3523.08,3759.32 ; C4.1 4080,4062.44 4050,4032.44 4050,3992.44 4067.44,3975 4177.44,3975 ; 4177.44,3975 4177.44,3935 C3.1 v1(4197.44,3884.05) 4273.31,3884.05 4303.31,3914.05 4303.31,4038.47 X1.4@4273.31,4068.47
  other v2: 3760.64,4270.64 3800.01,4270.64 3839.38,4270.64 3760.64,4309.99 3839.38,4310.01 3760.64,4349.38 3800.03,4349.35 3839.38,4349.38
GPIO35: CN1.4 R4.1 U1.40 | length 1453.5
  Top Layer w7.87: v1(3849.41,4135) 3919.41,4065 v1(3919.41,4055) ; v1(4039.41,4055) 4073.27,4088.86 4175.55,4088.86 4225.55,4138.86 v1(4225.55,4328.86)
  Bottom Layer w7.87: R4.1 3849.41,4129.07 v1(3849.41,4135) ; v1(3919.41,4055) v1(4039.41,4055) ; U1.40@3934.43,4238.86 3985.55,4238.86 4095.55,4348.86 4195.55,4348.86 4215.55,4328.86 4365.55,4328.86 4555.55,4138.86 CN1.4@4555.55,4118.86
I2S_BCK: U1.17 U3.13 | length 1348.4
  Top Layer w7.87: v1(3289.14,4024.16) 3289.14,3870.96 v1(3349.14,3810.96) ; v1(3489.14,4504.15) 3569.14,4584.15 3719.14,4584.15 v1(3749.14,4554.15)
  Bottom Layer w7.87: v1(3289.14,4024.16) 3269.14,4044.16 3269.14,4384.15 3279.14,4394.15 3379.14,4394.15 v1(3489.14,4504.15) ; U3.13 3309.14,3810.96 v1(3349.14,3810.96) ; U1.17 3729.14,4534.15 v1(3749.14,4554.15)
I2S_DATA: U1.15 U3.14 | length 873.8
  Bottom Layer w7.87: U3.14 3331.3,3830.5 3341.3,3840.5 3351.3,3840.5 3361.3,3830.5 3393.99,3830.5 3407.64,3844.16 3407.64,3964.16 3547.64,4104.15 3547.64,4354.15 3637.64,4444.15 U1.15
I2S_LRCK: U1.16 U3.15 | length 997
  Top Layer w7.87: v1(3255.02,3864.16) 3255.02,4255.79 3413.39,4414.15 v1(3713.39,4414.15)
  Bottom Layer w7.87: v1(3255.02,3864.16) 3295.02,3864.16 U3.15 ; v1(3713.39,4414.15) U1.16
LED_STAT: R17.1 U1.38 | length 415.7
  Top Layer w10: R17.1 4230.34,4389.66 v1(4250,4370)
  Bottom Layer w10: U1.38 3934.78,4270 3990,4270 4085.47,4365.47 4095.55,4365.47 4100.08,4370 v1(4250,4370)
OUTL: CN1.2 U3.6 | length 1257.6
  Top Layer w10: v1(3638.6,4035.55) 3668.6,4005.55 3684.45,4005.55 3834.45,3855.55 v1(3964.45,3855.55)
  Bottom Layer w10: U3.6 3619.14,3856.09 3648.6,3885.55 3648.6,4025.55 v1(3638.6,4035.55) ; v1(3964.45,3855.55) 4274.45,3855.55 4374.45,3955.55 CN1.2@4374.45,4075.55
OUTR: CN1.3 U3.7 | length 1569.6
  Top Layer w10: v1(3665.55,3830.5) 3775.55,3830.5 3935.55,3670.5 4335.55,3670.5 4505.55,3840.5 4505.55,4226.34 CN1.3@4555.55,4276.34
  Bottom Layer w10: U3.7 v1(3665.55,3830.5)
TF_CD: CARD1.CD R13.1 U1.42 | length 1168.1
  Top Layer w7.87: v1(3934.16,4187.64) 3958.92,4162.87 v1(3974.16,4162.87) ; v1(4024.16,4022.87) 4014.16,4032.87 v1(4014.16,4102.87) 4084.16,4102.87 v1(4134.15,4152.87)
  Bottom Layer w7.87: v1(3934.16,4187.64) U1.42 ; v1(3974.16,4162.87) 4014.16,4122.87 v1(4014.16,4102.87) ; v1(4024.16,4022.87) 3934.16,3932.87 3934.16,3815.05 CARD1.CD ; v1(4134.15,4152.87) 4134.15,4182.87 4160.94,4209.66 4365,4209.66 4375,4219.66 4375,4269.66 R13.1
TF_CLX: CARD1.5 U1.52 | length 790.4
  Bottom Layer w7.87: U1.52 3760.64,4065.34 3796.34,4029.64 3796.34,3759.64 4036.34,3519.64 CARD1.5
TF_CMD: CARD1.3 R15.1 U1.51 | length 1438.3
  Top Layer w7.87: v1(3816.34,4213.03) 3846.34,4183.03 3876.34,4183.03 3966.34,4093.03 ; v1(4136.34,4266.99) 4136.34,4193.03 4126.34,4183.03 4056.34,4183.03 3966.34,4093.03 ; v1(4216.34,3733.03) 4216.34,3743.03 3996.34,3963.03 3996.34,4043.03 3966.34,4073.03 3966.34,4093.03
  Bottom Layer w7.87: U1.51 3776.34,4193.03 3796.34,4213.03 v1(3816.34,4213.03) ; CARD1.3 4076.34,3433.03 4206.34,3563.03 4206.34,3723.03 v1(4216.34,3733.03) ; v1(4136.34,4266.99) R15.1
TF_DATA0: CARD1.7 R14.1 U1.43 | length 1113.2
  Bottom Layer w7.87: U1.43 3912.36,4165.85 3912.36,4162.28 ; CARD1.7 4036.34,3606.26 3916.34,3726.26 3916.34,4026.26 3896.34,4046.26 3896.34,4066.26 3912.36,4082.28 3912.36,4162.28 ; R14.1 4226.22,4296.14 4196.22,4326.14 4146.22,4326.14 4112.36,4292.28 4112.36,4242.28 4062.36,4192.28 3972.36,4192.28 3942.36,4162.28 3912.36,4162.28
USB_DN: U1.25 USBC1.A7 | length 1834.1
  Top Layer w7.87: v1(3345.12,3364.16) 3415.12,3434.16 3415.12,3494.16 3225.12,3684.16 3225.12,4254.15 3415.12,4444.15 3825.12,4444.15 v1(3855.12,4414.15)
  Bottom Layer w7.87: v1(3345.12,3364.16) 3355.12,3354.16 3355.12,3324.16 3364.44,3314.84 USBC1.A7 ; v1(3855.12,4414.15) U1.25
USB_DP: U1.26 USBC1.A6 | length 1925.9
  Top Layer w7.87: v1(3332.41,3335.7) 3312.41,3355.7 3312.41,3575.7 3202.41,3685.7 3202.41,4255.69 3410.86,4464.15 3480.86,4464.15 3580.86,4564.15 3700.86,4564.15 3750.86,4514.15 3840.86,4514.15 v1(3860.86,4494.15)
  Bottom Layer w7.87: v1(3332.41,3335.7) 3332.41,3325.7 3362.41,3295.7 3391.87,3295.7 USBC1.A6 ; v1(3860.86,4494.15) 3870.86,4484.15 U1.26
V_BAT: pad.1@3440,3645 SW1.4 U2.3 | length 1191.8
  Top Layer w10: v1(3323.1,3680.1) 3399.9,3680.1 v1(3400,3680)
  Bottom Layer w10: U2.3 3346.12,3657.07 v1(3323.1,3680.1) 3226.16,3680.1 3166.26,3740 3166.26,4320 SW1.4 ; v1(3400,3680) 3425,3655
V_LDO_IN: C1.2 LDO1.1 LDO1.3 R_BT.1 SW1.5 SW1.6 | length 3837.5
  Top Layer w10: SW1.6 SW1.5 3177.52,4410 3177.52,3677.33 v1(3277.52,3577.33) ; v1(3519.36,3315.46) v1(3655,3451.1) ; v1(3655,3595) 3934.13,3595 3995.62,3656.49 4341.36,3656.49 4519.57,3834.7 4519.57,3859.57 v1(4545,3885) ; R_BT.1 4141.58,4445.34 4248.54,4338.38 4248.54,4021.46 v1(4380,3890)
  Bottom Layer w10: v1(3277.52,3577.33) 3381.16,3577.33 C1.2 3511.16,3417.33 3478.3,3384.47 LDO1.3@3478.3,3364.47 ; LDO1.1 3498.76,3284.93 3518.3,3304.47 3518.3,3334.47 3488.3,3364.47 LDO1.3@3478.3,3364.47 ; LDO1.3 LDO1.3@3478.3,3364.47 ; v1(3655,3451.1) v1(3655,3595) ; v1(4380,3890) 4385,3885 v1(4545,3885)
V_USB: U2.4 USBC1.A4B9 USBC1.B4A9 | length 536.8
  Bottom Layer w10: U2.4 3372.41,3534.18 3432.41,3474.18 3432.41,3409.5 3422.41,3399.5 USBC1.B4A9 3362.41,3399.5 3352.41,3389.5 3322.41,3389.5 3302.41,3369.5 3302.41,3269.5 3361.39,3210.51 USBC1.A4B9
VCC: C2.1 C6.1 C7.1 CARD1.4 LDO1.5 R4.2 R5.1 R5.2 R6.2 R7.2 R8.2 R9.2 R10.2 R11.2 R12.2 R13.2 R14.2 R15.2 U1.2 U1.3 U1.4 U1.5 U1.6 U1.20 U1.29 U1.46 U1.55 U1.56 U3.1 U3.8 U3.11 U3.20 | length 5417
  Top Layer w7.87: v1(3620.3,3803.76) 3620.3,3863.76 v1(3690.3,3933.76) ; v1(3700.3,4247.84) 3710.3,4237.84 3730.3,4237.84 ; v1(3800.3,4145) 3826.71,4118.58 3826.71,4115 3823.13,4115 3730.3,4207.84 3730.3,4237.84 ; v1(3993.13,4217.84) 3863.13,4217.84 v1(3853.13,4207.84) 3823.13,4237.84 3730.3,4237.84
  Top Layer w10: v1(3342.9,3733.73) 3372.9,3763.73 v1(3372.9,3853.73) ; v1(3993.13,4217.84) 4103.13,4217.84 v1(4113.13,4207.84)
  Bottom Layer w7.87: 3580.3,3783.76 3600.3,3783.76 v1(3620.3,3803.76) ; U1.2 3670.3,4227.84 ; U1.6 U1.5 U1.4 U1.3 3670.3,4234.68 ; v1(3690.3,3933.76) 3690.3,4133.76 3680.3,4143.76 3680.3,4173.76 ; v1(3700.3,4247.84) 3680.3,4227.84 3677.14,4227.84 ; U1.55 U1.56 3695.56,4173.76 3680.3,4173.76 ; U1.20 3776.39,4471.09 3793.13,4487.84 3803.13,4487.84 3813.13,4497.84 3833.13,4517.84 3853.13,4517.84 ; v1(3800.3,4145) 3790.3,4135 3790.3,4085 3800.3,4075 3844.66,4075 3874.66,4105 R4.2 ; U1.46 3855.12,4205.85 v1(3853.13,4207.84) 3873.13,4207.84 3890,4224.7 3890,4394.7 3923.13,4427.84 ; R5.1@3885,4530 3861.61,4530 3853.13,4521.53 3853.13,4517.84 ; U1.29 3923.13,4423.38 3923.13,4427.84 ; v1(3993.13,4217.84) 4038.18,4217.84 R6.2 ; 3670.3,4227.84 3670.3,4234.68 ; 3670.3,4227.84 3677.14,4227.84 ; 3670.3,4234.68 3677.14,4227.84 ; 3677.14,4227.84 3690.3,4214.68 3690.3,4193.76 3680.3,4183.76 3680.3,4173.76 ; 3853.13,4517.84 3873.13,4517.84 3923.13,4467.84 3923.13,4427.84
  Bottom Layer w10: C6.1 3182.9,3834.66 3182.9,3948.24 3212.9,3978.24 C7.1@3224.32,3978.24 ; C7.1 C7.1@3224.32,3978.24 ; R7.2 R8.2 R9.2 3312.9,4177.44 3312.9,4158.24 ; U3.11 U3.11@3332.9,3753.73 ; U3.20 U3.20@3302.9,3978.24 ; v1(3342.9,3733.73) 3332.9,3743.73 U3.11@3332.9,3753.73 ; v1(3372.9,3853.73) 3372.9,3958.24 3352.9,3978.24 U3.20@3302.9,3978.24 ; R12.2 3418.58,4188.24 R12.2@3412.9,4188.24 ; R10.2 R11.2 3432.9,4262.44 3432.9,4208.24 R12.2@3412.9,4188.24 ; U3.1 3498.28,3984.05 3449.14,3934.91 3449.14,3814.91 3459.14,3804.91 U3.8 3559.14,3804.91 3580.3,3783.76 3580.3,3736.34 ; LDO1.5 3593.98,3309.77 C2.1 3840.3,3476.34 ; 3813.13,4497.84 3813.13,4518.13 R5.2@3830,4535 ; CARD1.4 3840.3,3476.34 ; v1(4113.13,4207.84) 4136.51,4207.84 R15.2 4254.14,4240.34 R14.2 4341.48,4236.82 R13.2 ; C7.1@3224.32,3978.24 U3.20@3302.9,3978.24 ; U3.20@3302.9,3978.24 3312.9,3988.24 3312.9,4158.24 ; 3312.9,4158.24 3382.9,4158.24 R12.2@3412.9,4188.24 ; U3.11@3332.9,3753.73 3360.3,3726.34 3570.3,3726.34 3580.3,3736.34 ; 3580.3,3736.34 3840.3,3476.34
pads on no net: CARD1.1 CARD1.2 CARD1.8 CARD1.10 CARD1.11 CARD1.12 CARD1.13 LDO1.4 SW1.1 SW1.3 SW1.7 U1.1 U1.7 U1.8 U1.18 U1.23 U1.24 U1.27 U1.28 U1.30 U1.31 U1.32 U1.33 U1.34 U1.35 U1.36 U1.37 U1.39 U1.41 U1.44 U1.45 U1.47 U1.48 U1.49 U1.50 U1.53 U1.54 U2.5 U3.5 U3.16 U3.17 U3.18 USBC1.B6 USBC1.B7 USBC1.B8
copper on no net: | length 39.2
  Bottom Layer w10: 3665.84,4302.12 3666.67,4301.3 3683.49,4301.3 3694.78,4290 v1(3700,4290)

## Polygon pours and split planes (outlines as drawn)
GND on Bottom Layer (solid, remove dead copper, pour order 2): 3000,4750 4710,4750 4710,3010 3000,3010
GND on Top Layer (solid, remove dead copper, pour order 0): 3020,4730 4710,4730 4710,3000 3020,3000

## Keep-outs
Board Outline Layer:
  lines w10: 3085,3118.94 ccw(c3163.74,3118.94) 3163.74,3040.2 4581.06,3040.2 ccw(c4581.06,3118.94) 4659.8,3118.94 4659.8,4536.26 ccw(c4581.06,4536.26) 4581.06,4615 3163.74,4615 ccw(c3163.74,4536.26) 3085,4536.26 3085,3118.94

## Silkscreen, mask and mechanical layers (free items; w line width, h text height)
Top Solder Mask Layer:
  drawing of 32 lines, arcs and shapes, not listed
Bottom Solder Mask Layer:
  drawing of 5 lines, arcs and shapes, not listed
